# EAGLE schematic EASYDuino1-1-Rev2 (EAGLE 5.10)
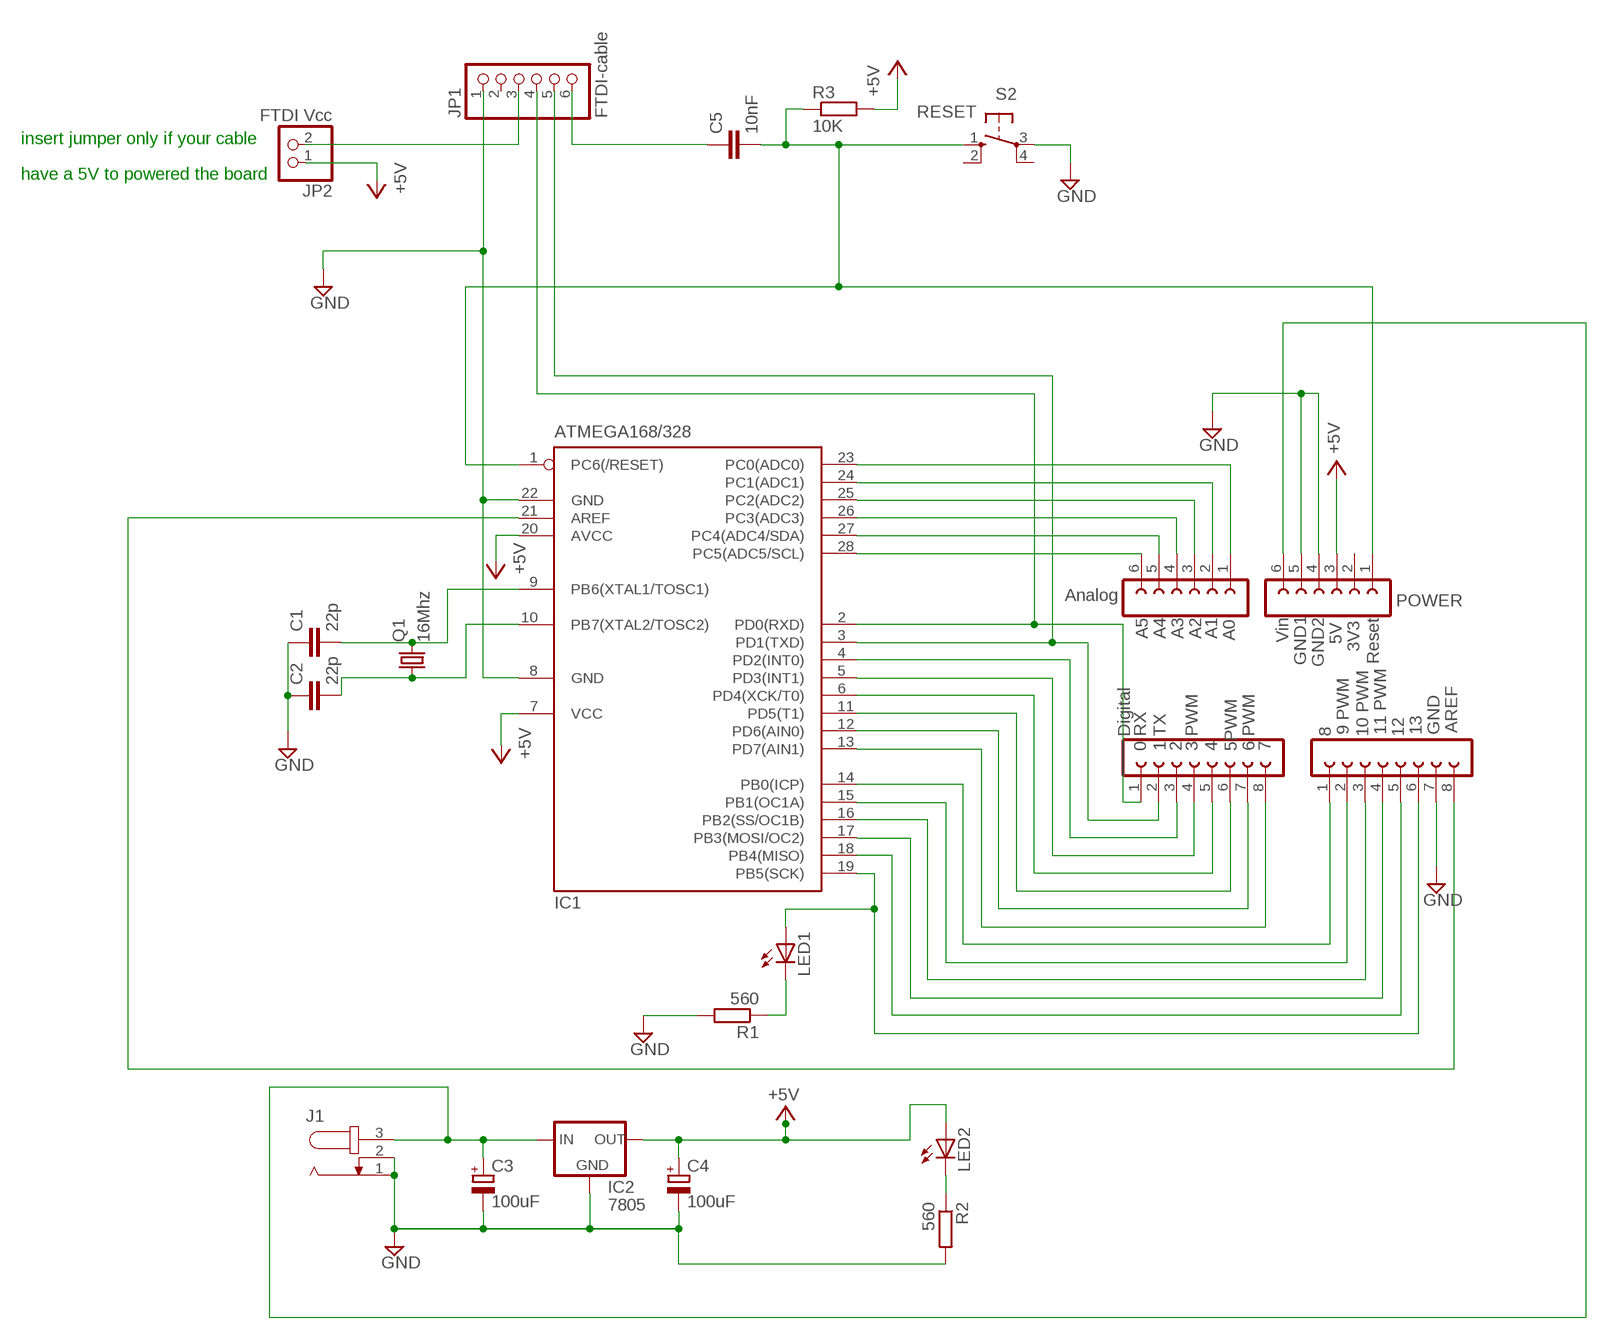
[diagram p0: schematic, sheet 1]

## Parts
C1  22p  C-EU025-024X044  [C025-024X044]
C2  22p  C-EU050-025X075  [C050-025X075]
C3  100uF  CPOL-EUE2,5-6E  [E2,5-6E]
C4  100uF  CPOL-EUE2,5-6E  [E2,5-6E]
C5  10nF  C-EU025-024X044  [C025-024X044]
IC1  ATMEGA168/328  MEGA8-P  [DIL28-3]
IC2  7805  V_REG_78XXSIDE  [78XXL]
J1  JACK-PLUG0  [SPC4077]
JP1  FTDI-cable  PINHD-1X6/90  [1X06/90]
JP2  FTDI Vcc  PINHD-1X2  [1X02]
LED1  LED3MM  [LED3MM]
LED2  LED3MM  [LED3MM]
Q1  16Mhz  CRYSTALHC49U-V  [HC49U-V]
R1  560  R-EU_0207/10  [0207/10]
R2  560  R-EU_0207/10  [0207/10]
R3  10K  R-EU_0207/10  [0207/10]
S2  RESET  10-XX  [B3F-10XX]
SV1  FE08-1  [FE08]
SV2  FE08-1  [FE08]
SV3  FE06-1  [FE06-MARCO]
SV4  FE06-1  [FE06-MARCO]

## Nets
+5V: C4.+ IC1.7(VCC) IC1.20(AVCC) IC2.OUT JP2.1 LED2.A R3.2 SV4.3
C-RESET: C5.1 JP1.6
GND: C1.1 C2.1 C3.- C4.- IC1.8(GND) IC1.22(GND) IC2.GND J1.1 J1.2 JP1.1 R1.2 R2.2 S2.3(P) SV2.7 SV4.4 SV4.5
N$2: IC1.4(PD2(INT0)) SV1.3
N$3: IC1.6(PD4(XCK/T0)) SV1.5
N$4: IC1.5(PD3(INT1)) SV1.4
N$5: IC1.3(PD1(TXD)) JP1.5 SV1.2
N$6: IC1.2(PD0(RXD)) JP1.4 SV1.1
N$7: IC1.19(PB5(SCK)) LED1.A SV2.6
N$8: IC1.18(PB4(MISO)) SV2.5
N$9: C1.2 IC1.9(PB6(XTAL1/TOSC1)) Q1.2
N$10: C2.2 IC1.10(PB7(XTAL2/TOSC2)) Q1.1
N$11: IC1.17(PB3(MOSI/OC2)) SV2.4
N$12: IC1.14(PB0(ICP)) SV2.1
N$13: IC1.13(PD7(AIN1)) SV1.8
N$14: IC1.12(PD6(AIN0)) SV1.7
N$15: IC1.11(PD5(T1)) SV1.6
N$16: IC1.16(PB2(SS/OC1B)) SV2.3
N$17: IC1.15(PB1(OC1A)) SV2.2
N$19: IC1.21(AREF) SV2.8
N$20: IC1.23(PC0(ADC0)) SV3.1
N$21: LED1.K(C) R1.1
N$23: LED2.K(C) R2.1
N$25: C5.2 IC1.1(PC6(/RESET)) R3.1 S2.1(S) SV4.1
N$26: IC1.24(PC1(ADC1)) SV3.2
N$27: IC1.25(PC2(ADC2)) SV3.3
N$28: IC1.26(PC3(ADC3)) SV3.4
N$29: IC1.27(PC4(ADC4/SDA)) SV3.5
N$30: IC1.28(PC5(ADC5/SCL)) SV3.6
N$34: JP1.3 JP2.2
VIN: C3.+ IC2.IN J1.3 SV4.6
Unconnected: JP1.2 S2.2(S1) S2.4(P1) SV4.2

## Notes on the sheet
- insert jumper only if your cable
- have a 5V to powered the board
- POWER
- Analog
- Vin | GND1 | GND2 | Reset
- 5V | 3V3
- A5 | A4 | A3 | A2 | A1 | A0
- Digital | 8 | 9 PWM | 10 PWM | 11 PWM | 12 | 13 | GND | AREF
- 0 RX | 1 TX | 2 | 3 PWM | 4 | 5PWM | 6 PWM | 7

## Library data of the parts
C1 C2 C5 = rcl:C-EU: CAPACITOR, European symbol
C3 C4 = rcl:CPOL-EU: POLARIZED CAPACITOR, European symbol
IC1 = atmel:MEGA8-P: MICROCONTROLLER 8 Kbytes FLASH, 1 kbytes SRAM, 512 bytes EEPROM, USART, 4-channel 10 bit ADC, 2-channel 8 bit ADC Pin compatible with Atmega48, ATMega88, ATMega168 Source: avr.lbr
IC2 = SparkFun:V_REG_78XX: Voltage Regulator Standard 7805 5V regulator. IGO (Input Ground Output). Spark Fun Electronics SKU : COM-00107
J1 = con-jack:JACK-PLUG: DC POWER JACK Power Jack, DC, Right Angle, Through Hole, Rated 5A at 16VDC, PC Terminals Distributor: Farnell (www.Farnell.de) Drawing: 84N1161.pdf / 84N1162.pdf Manufacturer: SPC Technology (www.spctechnology.com) Type: SPC4077 / SPC 4078
JP1 = pinhead:PINHD-1X6: PIN HEADER
JP2 = pinhead:PINHD-1X2: PIN HEADER
LED1 LED2 = led:LED: LED
Q1 = crystal:CRYSTAL: CRYSTAL
R1-R3 = resistor:R-EU_: RESISTOR, European symbol
S2 = switch-omron:10-XX: OMRON SWITCH
SV1 SV2 = con-lsta-Marco:FE08-1: FEMALE HEADER
SV3 SV4 = con-lsta-Marco:FE06-1: FEMALE HEADER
